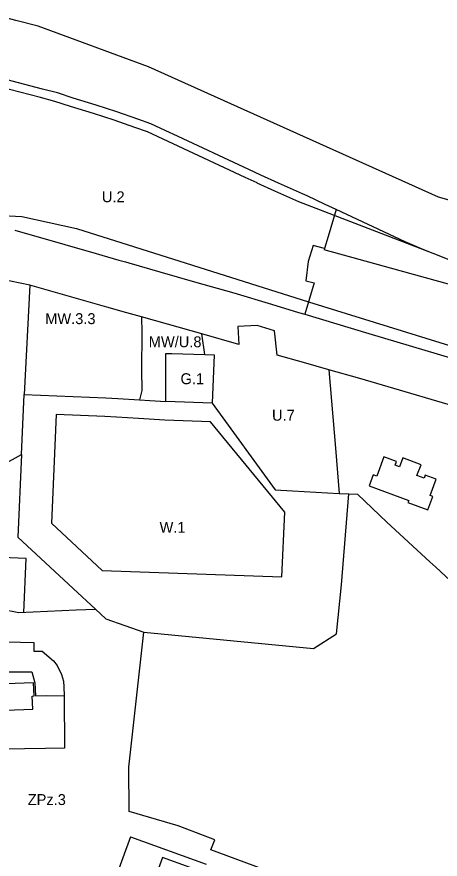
# Model space of a CAD drawing. Extents: x 7428239 to 7429836, y 5549133 to 5550853.
# Drawn here: x 7428761.2 to 7428955, y 5550266.4 to 5550651.7 of the extents above; entities that cross this region are included whole.
import ezdxf

# ---------------------------------------------------------------- set-up
doc = ezdxf.new("R2010")
doc.units = 0
for name, color, linetype in [('LIN_linie rozgraniczające', 7, 'Continuous'), ('LIN_nieprzekraczalna linia zabudowy', 7, 'Continuous'), ('LIN_obowiązująca linia zabudowy', 7, 'Continuous'), ('TXT_Oznaczenia Przeznaczenia', 7, 'Continuous')]:
    doc.layers.add(name, color=color, linetype=linetype)

msp = doc.modelspace()

# ---------------------------------------------------------------- linework, layer by layer
at = {"layer": 'LIN_linie rozgraniczające'}
for p, q in [((7428954.25, 5550569.24), (7428821.48, 5550628.82)), ((7428832.75, 5550598.08), (7428831.34, 5550598.74)), ((7428867.38, 5550581.94), (7428832.75, 5550598.08)), ((7428872.87, 5550579.38), (7428867.38, 5550581.94)), ((7428881.02, 5550575.7), (7428872.87, 5550579.38)), ((7428891.96, 5550570.78), (7428881.02, 5550575.7)), ((7428894.08, 5550569.83), (7428891.96, 5550570.78)), ((7428902.43, 5550565.94), (7428894.08, 5550569.83)), ((7428968.77, 5550565.19), (7428954.25, 5550569.24)), ((7428907.38, 5550563.62), (7428902.43, 5550565.94)), ((7428939.03, 5550548.87), (7428907.38, 5550563.62)), ((7428760.3, 5550554.13), (7428783.21, 5550547.57)), ((7428946.44, 5550545.6), (7428939.03, 5550548.87)), ((7428783.21, 5550547.57), (7428797.56, 5550543.46)), ((7428951.77, 5550543.44), (7428946.44, 5550545.6)), ((7428797.56, 5550543.46), (7428807.95, 5550540.48)), ((7428973.82, 5550534.74), (7428951.77, 5550543.44)), ((7428807.95, 5550540.48), (7428810.93, 5550539.63)), ((7428810.93, 5550539.63), (7428812.48, 5550539.19)), ((7428812.48, 5550539.19), (7428826.71, 5550535.11)), ((7428826.71, 5550535.11), (7428842.52, 5550530.58)), ((7428767.16, 5550528.95), (7428753.91, 5550531.68)), ((7428842.52, 5550530.58), (7428860.55, 5550525.42)), ((7428767.16, 5550528.95), (7428764.53, 5550479.02)), ((7428860.55, 5550525.42), (7428877.73, 5550520.27)), ((7428877.73, 5550520.27), (7428890.18, 5550516.55)), ((7428890.18, 5550516.55), (7428893.06, 5550515.69)), ((7428893.06, 5550515.69), (7428922.42, 5550506.91)), ((7428847.35, 5550497.29), (7428845.97, 5550506.79)), ((7428922.42, 5550506.91), (7428960.75, 5550495.46)), ((7428918.22, 5550486.23), (7428904.01, 5550490.32)), ((7428764.53, 5550479.02), (7428801.94, 5550477.4)), ((7428801.94, 5550477.4), (7428807.41, 5550477.08)), ((7428807.41, 5550477.08), (7428817.39, 5550476.5)), ((7428817.39, 5550476.5), (7428822.07, 5550476.22)), ((7428822.07, 5550476.22), (7428829.37, 5550475.79)), ((7428850.62, 5550475), (7428879.48, 5550435.41)), ((7428879.48, 5550435.41), (7428887.47, 5550434.95)), ((7428887.47, 5550434.95), (7428898.15, 5550434.33)), ((7428898.15, 5550434.33), (7428908.8, 5550433.72)), ((7428908.8, 5550433.72), (7428913.19, 5550433.54)), ((7428913.19, 5550433.54), (7428917.19, 5550433.38)), ((7428917.19, 5550433.38), (7428930.65, 5550420.64)), ((7428930.65, 5550420.64), (7428950.35, 5550402.37)), ((7428950.35, 5550402.37), (7428952.96, 5550399.93)), ((7428952.96, 5550399.93), (7428978.86, 5550375.86)), ((7428907.55, 5550369.48), (7428909.86, 5550391.95)), ((7428812.51, 5550308.56), (7428819.32, 5550370.19)), ((7428819.32, 5550370.19), (7428897.05, 5550362.86)), ((7428897.05, 5550362.86), (7428907.55, 5550369.48)), ((7428782.83, 5550341.17), (7428782.97, 5550317.23)), ((7428812.63, 5550288.19), (7428812.51, 5550308.56)), ((7428835.11, 5550281.59), (7428812.63, 5550288.19)), ((7428851.79, 5550275.33), (7428835.11, 5550281.59)), ((7428813.18, 5550276.63), (7428795.72, 5550228.45)), ((7428850, 5550270.61), (7428851.79, 5550275.33)), ((7428924.77, 5550243.28), (7428850, 5550270.61))]:
    msp.add_line(p, q, dxfattribs=at)
for points in [[(7428821.48, 5550628.82), (7428770.94, 5550647.44), (7428760.76, 5550650.1), (7428735.98, 5550656.57), (7428719.28, 5550662.75)], [(7428831.34, 5550598.74), (7428822.59, 5550602.83), (7428816.6, 5550604.92), (7428806.98, 5550608.3), (7428797.5, 5550611.31), (7428787, 5550614.62), (7428779.77, 5550616.92), (7428773.03, 5550618.67), (7428753.85, 5550623.63)], [(7428907.38, 5550563.62), (7428903.7, 5550551.3), (7428902.02, 5550545.78), (7428901.86, 5550545.18)], [(7428902.02, 5550545.78), (7428896.89, 5550547.21), (7428894.66, 5550539.87), (7428893.53, 5550531.05), (7428897.35, 5550530.06)], [(7429057.67, 5550497.66), (7429057.91, 5550498.53), (7429048, 5550501.23), (7429023.24, 5550507.96), (7429023.67, 5550509.82), (7428988.72, 5550519.24), (7428989.21, 5550521.09), (7428901.86, 5550545.18)], [(7428897.35, 5550530.06), (7428893.06, 5550515.69)], [(7428904.01, 5550490.32), (7428892.4, 5550493.61), (7428880.38, 5550497), (7428879.12, 5550508.1), (7428871.25, 5550510.52), (7428862.42, 5550510.12), (7428862.92, 5550501.91), (7428845.97, 5550506.79), (7428830.16, 5550511.17), (7428818.36, 5550514.45), (7428811.51, 5550516.35), (7428802.35, 5550518.89), (7428767.16, 5550528.95)], [(7428818.36, 5550514.45), (7428818.38, 5550507.19), (7428818.36, 5550490.13), (7428818.42, 5550480.86), (7428817.39, 5550476.5)], [(7428904.01, 5550490.32), (7428907.05, 5550454.39), (7428908.8, 5550433.72)], [(7428974.19, 5550469.76), (7428918.22, 5550486.23)], [(7428713.31, 5550433.25), (7428718.88, 5550434.46), (7428729.82, 5550436.8), (7428746.05, 5550442.15), (7428763.33, 5550451.58), (7428764.53, 5550479.02)], [(7428763.33, 5550451.58), (7428761.68, 5550413.78), (7428787.06, 5550390.21), (7428797.19, 5550380.81)], [(7428909.86, 5550391.95), (7428913.19, 5550433.54)], [(7428613.32, 5550403.11), (7428625.75, 5550403.58), (7428634.13, 5550403.5), (7428638.48, 5550403.88), (7428650.8, 5550403.72), (7428665.4, 5550405.77), (7428671.06, 5550405.31), (7428684.46, 5550405.98), (7428687.55, 5550406.08), (7428692.47, 5550386.04), (7428705.26, 5550386.53), (7428714.6, 5550386.89), (7428720.24, 5550387.11), (7428722.64, 5550387.21), (7428738.83, 5550383.93), (7428754.33, 5550380.81), (7428762.17, 5550379.23), (7428788.4, 5550380.41), (7428797.19, 5550380.81)], [(7428797.19, 5550380.81), (7428801.96, 5550376.39), (7428819.32, 5550370.19)], [(7428750.63, 5550365.96), (7428768.98, 5550365.54), (7428768.93, 5550361.62), (7428772.84, 5550361.62), (7428778.02, 5550357.11), (7428779.65, 5550355.05), (7428781.64, 5550350.96), (7428782.59, 5550347.84), (7428782.81, 5550345.27), (7428782.83, 5550341.17)], [(7428649.94, 5550353.45), (7428656.43, 5550353.73), (7428684.28, 5550352.94), (7428697.62, 5550352.87), (7428711.92, 5550352.78), (7428725.12, 5550352.65), (7428739.82, 5550352.33), (7428754.12, 5550352.06), (7428768.05, 5550352.1), (7428769.51, 5550347.13), (7428769.78, 5550341.08), (7428774.92, 5550341.24), (7428782.83, 5550341.17)], [(7428774.34, 5550317.09), (7428726, 5550316.32), (7428726.24, 5550301.32), (7428726.42, 5550290.09), (7428716.31, 5550259.45)], [(7428782.97, 5550317.23), (7428774.34, 5550317.09)], [(7428813.18, 5550276.63), (7428847.92, 5550264.11)]]:
    msp.add_lwpolyline(points, dxfattribs=at)
msp.add_lwpolyline([(7428829.44, 5550489.08), (7428829.48, 5550497.8), (7428832.12, 5550497.72), (7428847.35, 5550497.29), (7428851.49, 5550497.17), (7428850.62, 5550475), (7428829.37, 5550475.79)], close=True, dxfattribs=at)
at = {"layer": 'LIN_nieprzekraczalna linia zabudowy'}
for p, q in [((7428865.69, 5550578.31), (7428820.96, 5550599.16)), ((7428871.18, 5550575.75), (7428865.69, 5550578.31)), ((7428879.37, 5550572.05), (7428871.22, 5550575.73)), ((7428890.32, 5550567.13), (7428879.38, 5550572.05))]:
    msp.add_line(p, q, dxfattribs=at)
for points in [[(7428820.96, 5550599.16), (7428815.28, 5550601.14), (7428805.71, 5550604.51), (7428796.29, 5550607.5), (7428785.79, 5550610.81), (7428778.66, 5550613.08), (7428772.03, 5550614.8), (7428753.03, 5550619.71), (7428748.57, 5550620.42), (7428729.52, 5550623.42), (7428718.27, 5550624.95), (7428717.84, 5550624.92)], [(7429059.67, 5550504.98), (7429049.62, 5550507.57), (7428988.94, 5550529.2), (7428973.82, 5550534.74), (7428951.77, 5550543.44), (7428890.28, 5550567.15)], [(7428669.52, 5550545.96), (7428703.88, 5550555.62), (7428719.96, 5550558.83), (7428734.33, 5550560.82), (7428751.87, 5550560.96), (7428763.53, 5550560.38), (7428788.54, 5550554.92), (7428894.78, 5550521.44)], [(7428904.01, 5550490.32), (7428892.4, 5550493.61), (7428880.38, 5550497), (7428879.12, 5550508.1), (7428871.25, 5550510.52), (7428862.42, 5550510.12), (7428862.92, 5550501.91), (7428845.97, 5550506.79), (7428830.16, 5550511.17), (7428818.36, 5550514.45), (7428811.51, 5550516.35), (7428802.35, 5550518.89), (7428767.16, 5550528.95)], [(7428894.78, 5550521.44), (7429027.73, 5550480.16), (7429051.28, 5550473.1)], [(7428779.19, 5550469.82), (7428777.02, 5550420.07), (7428800.29, 5550398.46)], [(7428849.94, 5550466.46), (7428828.96, 5550467.24), (7428816.89, 5550467.96), (7428806.91, 5550468.54), (7428801.5, 5550468.85), (7428779.19, 5550469.82)], [(7428883.89, 5550425.13), (7428849.94, 5550466.46)], [(7428764.39, 5550379.33), (7428765.46, 5550403.92), (7428750.66, 5550404.56), (7428751.5, 5550423.17), (7428751.65, 5550425), (7428751.88, 5550429.36), (7428699.31, 5550425.39)], [(7428800.29, 5550398.46), (7428882.5, 5550395.58), (7428883.89, 5550425.13)], [(7428840.5, 5550262.62), (7428827.86, 5550267.22), (7428813.4, 5550227.15), (7428826.08, 5550222.62), (7428840.5, 5550262.62)]]:
    msp.add_lwpolyline(points, dxfattribs=at)
at = {"layer": 'LIN_obowiązująca linia zabudowy'}
msp.add_lwpolyline([(7428922.44, 5550437.27), (7428940.67, 5550430.56), (7428940.28, 5550429.52), (7428949.36, 5550426.18), (7428951.61, 5550432.3), (7428950.4, 5550432.75), (7428953.16, 5550440.22), (7428948.18, 5550442.06), (7428947.68, 5550440.71), (7428944.4, 5550441.92), (7428946.25, 5550446.81), (7428937.87, 5550449.96), (7428936.4, 5550445.94), (7428934.37, 5550446.69), (7428934.97, 5550448.32), (7428929.24, 5550450.43), (7428925.98, 5550441.57), (7428924.29, 5550442.19)], close=True, dxfattribs=at)
msp.add_lwpolyline([(7428739.31, 5550333.91), (7428768.55, 5550335), (7428768.25, 5550341.01), (7428769.19, 5550341.06), (7428768.9, 5550347.15), (7428739.03, 5550346.04)], dxfattribs=at)

# ---------------------------------------------------------------- texts
at = {"layer": 'TXT_Oznaczenia Przeznaczenia'}
for s, p in [('U.2', (7428800.16, 5550566.93)), ('MW.3.3', (7428774.21, 5550511.18)), ('MW/U.8', (7428821.61, 5550500.6)), ('G.1', (7428836.15, 5550483.7)), ('U.7', (7428878.04, 5550467)), ('W.1', (7428826.56, 5550415.73)), ('ZPz.3', (7428766.2, 5550291.17))]:
    msp.add_text(s, height=5, dxfattribs=at).set_placement(p)

doc.saveas('drawing.dxf')
